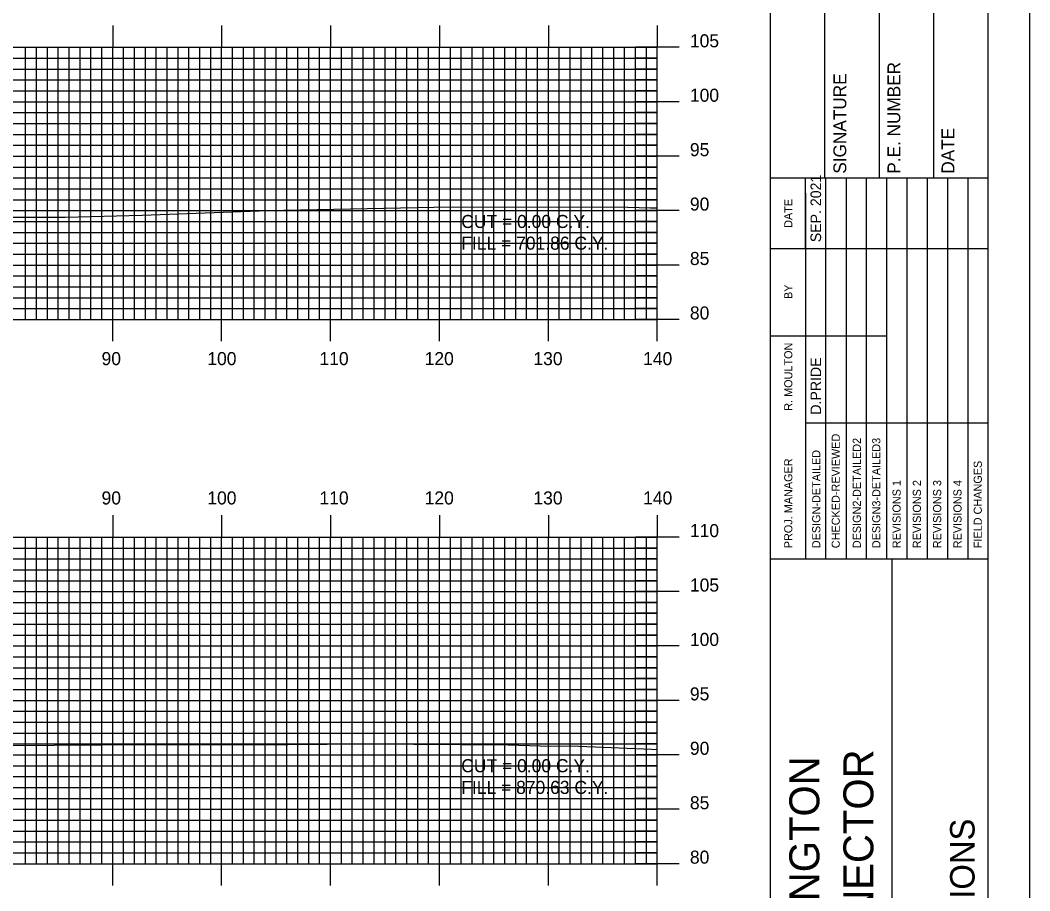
# Model space of a CAD drawing. Extents: x 1272 to 1616, y -1658 to -1438.
# Drawn here: x 1519.7 to 1612.4, y -1592.1 to -1512.1 of the extents above; entities that cross this region are included whole.
import ezdxf

# ---------------------------------------------------------------- set-up
doc = ezdxf.new("R2010")
doc.units = 0
for name, color, linetype in [('BORDER', 7, 'Continuous'), ('D_Text_Standard', 7, 'Continuous'), ('H_V ANNOTATION', 7, 'Continuous'), ('MAJOR', 7, 'Continuous'), ('MINOR', 7, 'Continuous'), ('PLOT BOUNDARY', 7, 'Continuous'), ('S_Roadway_Centerline', 7, 'Continuous')]:
    doc.layers.add(name, color=color, linetype=linetype)

msp = doc.modelspace()

# ---------------------------------------------------------------- linework, layer by layer
at = {"layer": 'BORDER'}
for p, q in [((1588.561, -1651.604), (1588.561, -1441.604)), ((1593.561, -1526.599), (1593.561, -1509.304)), ((1598.561, -1526.599), (1598.561, -1509.304)), ((1603.561, -1526.599), (1603.561, -1509.304)), ((1588.561, -1526.599), (1608.561, -1526.599)), ((1588.561, -1561.599), (1608.561, -1561.599)), ((1599.743, -1631.599), (1599.743, -1561.599))]:
    msp.add_line(p, q, dxfattribs=at)
msp.add_lwpolyline([(1288.561, -1651.604), (1608.561, -1651.604), (1608.561, -1441.604), (1288.561, -1441.604)], close=True, dxfattribs=at)
for points in [[(1591.79, -1533.099), (1591.79, -1526.599)], [(1593.655, -1561.593), (1593.655, -1526.599)], [(1595.519, -1526.599), (1595.519, -1561.593)], [(1597.382, -1561.593), (1597.382, -1526.599)], [(1599.246, -1561.593), (1599.246, -1526.599)], [(1601.109, -1561.593), (1601.109, -1526.599)], [(1602.972, -1561.593), (1602.972, -1526.599)], [(1604.836, -1561.593), (1604.836, -1526.599)], [(1606.699, -1561.593), (1606.699, -1526.599)], [(1591.792, -1561.593), (1591.792, -1528.01)], [(1588.561, -1533.099), (1608.561, -1533.099)], [(1588.561, -1541.099), (1591.792, -1541.099)], [(1591.79, -1541.099), (1599.244, -1541.099)], [(1591.79, -1549.099), (1608.561, -1549.099)]]:
    msp.add_lwpolyline(points, dxfattribs=at)
at = {"layer": 'MAJOR'}
for p, q in [((1528.161, -1512.6), (1528.161, -1514.604)), ((1538.161, -1512.6), (1538.161, -1514.604)), ((1548.161, -1512.6), (1548.161, -1514.604)), ((1558.161, -1512.6), (1558.161, -1514.604)), ((1568.161, -1512.6), (1568.161, -1514.604)), ((1578.161, -1512.6), (1578.161, -1514.604)), ((1298.161, -1514.604), (1578.161, -1514.604)), ((1298.161, -1514.604), (1578.161, -1514.604)), ((1528.161, -1539.604), (1528.161, -1514.604)), ((1538.161, -1539.604), (1538.161, -1514.604)), ((1548.161, -1539.604), (1548.161, -1514.604)), ((1558.161, -1539.604), (1558.161, -1514.604)), ((1568.161, -1539.604), (1568.161, -1514.604)), ((1580.165, -1514.604), (1576.157, -1514.604)), ((1578.161, -1539.604), (1578.161, -1514.604)), ((1578.161, -1539.604), (1578.161, -1514.604)), ((1298.161, -1519.604), (1578.161, -1519.604)), ((1580.165, -1519.604), (1576.157, -1519.604)), ((1298.161, -1524.604), (1578.161, -1524.604)), ((1580.165, -1524.604), (1576.157, -1524.604)), ((1298.161, -1529.604), (1578.161, -1529.604)), ((1580.165, -1529.604), (1576.157, -1529.604)), ((1298.161, -1534.604), (1578.161, -1534.604)), ((1580.165, -1534.604), (1576.157, -1534.604)), ((1298.161, -1539.604), (1578.161, -1539.604)), ((1298.161, -1539.604), (1578.161, -1539.604)), ((1528.161, -1541.608), (1528.161, -1539.604)), ((1538.161, -1541.608), (1538.161, -1539.604)), ((1548.161, -1541.608), (1548.161, -1539.604)), ((1558.161, -1541.608), (1558.161, -1539.604)), ((1568.161, -1541.608), (1568.161, -1539.604)), ((1580.165, -1539.604), (1576.157, -1539.604)), ((1578.161, -1541.608), (1578.161, -1539.604)), ((1528.161, -1557.6), (1528.161, -1559.604)), ((1538.161, -1557.6), (1538.161, -1559.604)), ((1548.161, -1557.6), (1548.161, -1559.604)), ((1558.161, -1557.6), (1558.161, -1559.604)), ((1568.161, -1557.6), (1568.161, -1559.604)), ((1578.161, -1557.6), (1578.161, -1559.604)), ((1298.161, -1559.604), (1578.161, -1559.604)), ((1298.161, -1559.604), (1578.161, -1559.604)), ((1528.161, -1589.604), (1528.161, -1559.604)), ((1538.161, -1589.604), (1538.161, -1559.604)), ((1548.161, -1589.604), (1548.161, -1559.604)), ((1558.161, -1589.604), (1558.161, -1559.604)), ((1568.161, -1589.604), (1568.161, -1559.604)), ((1580.165, -1559.604), (1576.157, -1559.604)), ((1578.161, -1589.604), (1578.161, -1559.604)), ((1578.161, -1589.604), (1578.161, -1559.604)), ((1298.161, -1564.604), (1578.161, -1564.604)), ((1580.165, -1564.604), (1576.157, -1564.604)), ((1298.161, -1569.604), (1578.161, -1569.604)), ((1580.165, -1569.604), (1576.157, -1569.604)), ((1298.161, -1574.604), (1578.161, -1574.604)), ((1580.165, -1574.604), (1576.157, -1574.604)), ((1298.161, -1579.604), (1578.161, -1579.604)), ((1580.165, -1579.604), (1576.157, -1579.604)), ((1298.161, -1584.604), (1578.161, -1584.604)), ((1580.165, -1584.604), (1576.157, -1584.604)), ((1298.161, -1589.604), (1578.161, -1589.604)), ((1298.161, -1589.604), (1578.161, -1589.604)), ((1528.161, -1591.608), (1528.161, -1589.604)), ((1538.161, -1591.608), (1538.161, -1589.604)), ((1548.161, -1591.608), (1548.161, -1589.604)), ((1558.161, -1591.608), (1558.161, -1589.604)), ((1568.161, -1591.608), (1568.161, -1589.604)), ((1580.165, -1589.604), (1576.157, -1589.604)), ((1578.161, -1591.608), (1578.161, -1589.604))]:
    msp.add_line(p, q, dxfattribs=at)
at = {"layer": 'MINOR'}
for p, q in [((1520.161, -1539.604), (1520.161, -1514.604)), ((1521.161, -1539.604), (1521.161, -1514.604)), ((1522.161, -1539.604), (1522.161, -1514.604)), ((1523.161, -1539.604), (1523.161, -1514.604)), ((1524.161, -1539.604), (1524.161, -1514.604)), ((1525.161, -1539.604), (1525.161, -1514.604)), ((1526.161, -1539.604), (1526.161, -1514.604)), ((1527.161, -1539.604), (1527.161, -1514.604)), ((1529.161, -1539.604), (1529.161, -1514.604)), ((1530.161, -1539.604), (1530.161, -1514.604)), ((1531.161, -1539.604), (1531.161, -1514.604)), ((1532.161, -1539.604), (1532.161, -1514.604)), ((1533.161, -1539.604), (1533.161, -1514.604)), ((1534.161, -1539.604), (1534.161, -1514.604)), ((1535.161, -1539.604), (1535.161, -1514.604)), ((1536.161, -1539.604), (1536.161, -1514.604)), ((1537.161, -1539.604), (1537.161, -1514.604)), ((1539.161, -1539.604), (1539.161, -1514.604)), ((1540.161, -1539.604), (1540.161, -1514.604)), ((1541.161, -1539.604), (1541.161, -1514.604)), ((1542.161, -1539.604), (1542.161, -1514.604)), ((1543.161, -1539.604), (1543.161, -1514.604)), ((1544.161, -1539.604), (1544.161, -1514.604)), ((1545.161, -1539.604), (1545.161, -1514.604)), ((1546.161, -1539.604), (1546.161, -1514.604)), ((1547.161, -1539.604), (1547.161, -1514.604)), ((1549.161, -1539.604), (1549.161, -1514.604)), ((1550.161, -1539.604), (1550.161, -1514.604)), ((1551.161, -1539.604), (1551.161, -1514.604)), ((1552.161, -1539.604), (1552.161, -1514.604)), ((1553.161, -1539.604), (1553.161, -1514.604)), ((1554.161, -1539.604), (1554.161, -1514.604)), ((1555.161, -1539.604), (1555.161, -1514.604)), ((1556.161, -1539.604), (1556.161, -1514.604)), ((1557.161, -1539.604), (1557.161, -1514.604)), ((1559.161, -1539.604), (1559.161, -1514.604)), ((1560.161, -1539.604), (1560.161, -1514.604)), ((1561.161, -1539.604), (1561.161, -1514.604)), ((1562.161, -1539.604), (1562.161, -1514.604)), ((1563.161, -1539.604), (1563.161, -1514.604)), ((1564.161, -1539.604), (1564.161, -1514.604)), ((1565.161, -1539.604), (1565.161, -1514.604)), ((1566.161, -1539.604), (1566.161, -1514.604)), ((1567.161, -1539.604), (1567.161, -1514.604)), ((1569.161, -1539.604), (1569.161, -1514.604)), ((1570.161, -1539.604), (1570.161, -1514.604)), ((1571.161, -1539.604), (1571.161, -1514.604)), ((1572.161, -1539.604), (1572.161, -1514.604)), ((1573.161, -1539.604), (1573.161, -1514.604)), ((1574.161, -1539.604), (1574.161, -1514.604)), ((1575.161, -1539.604), (1575.161, -1514.604)), ((1576.161, -1539.604), (1576.161, -1514.604)), ((1577.161, -1539.604), (1577.161, -1514.604)), ((1298.161, -1515.604), (1578.161, -1515.604)), ((1578.161, -1515.604), (1576.157, -1515.604)), ((1298.161, -1516.604), (1578.161, -1516.604)), ((1578.161, -1516.604), (1576.157, -1516.604)), ((1298.161, -1517.604), (1578.161, -1517.604)), ((1578.161, -1517.604), (1576.157, -1517.604)), ((1298.161, -1518.604), (1578.161, -1518.604)), ((1578.161, -1518.604), (1576.157, -1518.604)), ((1298.161, -1520.604), (1578.161, -1520.604)), ((1578.161, -1520.604), (1576.157, -1520.604)), ((1298.161, -1521.604), (1578.161, -1521.604)), ((1578.161, -1521.604), (1576.157, -1521.604)), ((1298.161, -1522.604), (1578.161, -1522.604)), ((1578.161, -1522.604), (1576.157, -1522.604)), ((1298.161, -1523.604), (1578.161, -1523.604)), ((1578.161, -1523.604), (1576.157, -1523.604)), ((1298.161, -1525.604), (1578.161, -1525.604)), ((1578.161, -1525.604), (1576.157, -1525.604)), ((1298.161, -1526.604), (1578.161, -1526.604)), ((1578.161, -1526.604), (1576.157, -1526.604)), ((1298.161, -1527.604), (1578.161, -1527.604)), ((1578.161, -1527.604), (1576.157, -1527.604)), ((1298.161, -1528.604), (1578.161, -1528.604)), ((1578.161, -1528.604), (1576.157, -1528.604)), ((1298.161, -1530.604), (1578.161, -1530.604)), ((1578.161, -1530.604), (1576.157, -1530.604)), ((1298.161, -1531.604), (1578.161, -1531.604)), ((1578.161, -1531.604), (1576.157, -1531.604)), ((1298.161, -1532.604), (1578.161, -1532.604)), ((1578.161, -1532.604), (1576.157, -1532.604)), ((1298.161, -1533.604), (1578.161, -1533.604)), ((1578.161, -1533.604), (1576.157, -1533.604)), ((1298.161, -1535.604), (1578.161, -1535.604)), ((1578.161, -1535.604), (1576.157, -1535.604)), ((1298.161, -1536.604), (1578.161, -1536.604)), ((1578.161, -1536.604), (1576.157, -1536.604)), ((1298.161, -1537.604), (1578.161, -1537.604)), ((1578.161, -1537.604), (1576.157, -1537.604)), ((1298.161, -1538.604), (1578.161, -1538.604)), ((1578.161, -1538.604), (1576.157, -1538.604)), ((1520.161, -1589.604), (1520.161, -1559.604)), ((1521.161, -1589.604), (1521.161, -1559.604)), ((1522.161, -1589.604), (1522.161, -1559.604)), ((1523.161, -1589.604), (1523.161, -1559.604)), ((1524.161, -1589.604), (1524.161, -1559.604)), ((1525.161, -1589.604), (1525.161, -1559.604)), ((1526.161, -1589.604), (1526.161, -1559.604)), ((1527.161, -1589.604), (1527.161, -1559.604)), ((1529.161, -1589.604), (1529.161, -1559.604)), ((1530.161, -1589.604), (1530.161, -1559.604)), ((1531.161, -1589.604), (1531.161, -1559.604)), ((1532.161, -1589.604), (1532.161, -1559.604)), ((1533.161, -1589.604), (1533.161, -1559.604)), ((1534.161, -1589.604), (1534.161, -1559.604)), ((1535.161, -1589.604), (1535.161, -1559.604)), ((1536.161, -1589.604), (1536.161, -1559.604)), ((1537.161, -1589.604), (1537.161, -1559.604)), ((1539.161, -1589.604), (1539.161, -1559.604)), ((1540.161, -1589.604), (1540.161, -1559.604)), ((1541.161, -1589.604), (1541.161, -1559.604)), ((1542.161, -1589.604), (1542.161, -1559.604)), ((1543.161, -1589.604), (1543.161, -1559.604)), ((1544.161, -1589.604), (1544.161, -1559.604)), ((1545.161, -1589.604), (1545.161, -1559.604)), ((1546.161, -1589.604), (1546.161, -1559.604)), ((1547.161, -1589.604), (1547.161, -1559.604)), ((1549.161, -1589.604), (1549.161, -1559.604)), ((1550.161, -1589.604), (1550.161, -1559.604)), ((1551.161, -1589.604), (1551.161, -1559.604)), ((1552.161, -1589.604), (1552.161, -1559.604)), ((1553.161, -1589.604), (1553.161, -1559.604)), ((1554.161, -1589.604), (1554.161, -1559.604)), ((1555.161, -1589.604), (1555.161, -1559.604)), ((1556.161, -1589.604), (1556.161, -1559.604)), ((1557.161, -1589.604), (1557.161, -1559.604)), ((1559.161, -1589.604), (1559.161, -1559.604)), ((1560.161, -1589.604), (1560.161, -1559.604)), ((1561.161, -1589.604), (1561.161, -1559.604)), ((1562.161, -1589.604), (1562.161, -1559.604)), ((1563.161, -1589.604), (1563.161, -1559.604)), ((1564.161, -1589.604), (1564.161, -1559.604)), ((1565.161, -1589.604), (1565.161, -1559.604)), ((1566.161, -1589.604), (1566.161, -1559.604)), ((1567.161, -1589.604), (1567.161, -1559.604)), ((1569.161, -1589.604), (1569.161, -1559.604)), ((1570.161, -1589.604), (1570.161, -1559.604)), ((1571.161, -1589.604), (1571.161, -1559.604)), ((1572.161, -1589.604), (1572.161, -1559.604)), ((1573.161, -1589.604), (1573.161, -1559.604)), ((1574.161, -1589.604), (1574.161, -1559.604)), ((1575.161, -1589.604), (1575.161, -1559.604)), ((1576.161, -1589.604), (1576.161, -1559.604)), ((1577.161, -1589.604), (1577.161, -1559.604)), ((1298.161, -1560.604), (1578.161, -1560.604)), ((1578.161, -1560.604), (1576.157, -1560.604)), ((1298.161, -1561.604), (1578.161, -1561.604)), ((1578.161, -1561.604), (1576.157, -1561.604)), ((1298.161, -1562.604), (1578.161, -1562.604)), ((1578.161, -1562.604), (1576.157, -1562.604)), ((1298.161, -1563.604), (1578.161, -1563.604)), ((1578.161, -1563.604), (1576.157, -1563.604)), ((1298.161, -1565.604), (1578.161, -1565.604)), ((1578.161, -1565.604), (1576.157, -1565.604)), ((1298.161, -1566.604), (1578.161, -1566.604)), ((1578.161, -1566.604), (1576.157, -1566.604)), ((1298.161, -1567.604), (1578.161, -1567.604)), ((1578.161, -1567.604), (1576.157, -1567.604)), ((1298.161, -1568.604), (1578.161, -1568.604)), ((1578.161, -1568.604), (1576.157, -1568.604)), ((1298.161, -1570.604), (1578.161, -1570.604)), ((1578.161, -1570.604), (1576.157, -1570.604)), ((1298.161, -1571.604), (1578.161, -1571.604)), ((1578.161, -1571.604), (1576.157, -1571.604)), ((1298.161, -1572.604), (1578.161, -1572.604)), ((1578.161, -1572.604), (1576.157, -1572.604)), ((1298.161, -1573.604), (1578.161, -1573.604)), ((1578.161, -1573.604), (1576.157, -1573.604)), ((1298.161, -1575.604), (1578.161, -1575.604)), ((1578.161, -1575.604), (1576.157, -1575.604)), ((1298.161, -1576.604), (1578.161, -1576.604)), ((1578.161, -1576.604), (1576.157, -1576.604)), ((1298.161, -1577.604), (1578.161, -1577.604)), ((1578.161, -1577.604), (1576.157, -1577.604)), ((1298.161, -1578.604), (1578.161, -1578.604)), ((1578.161, -1578.604), (1576.157, -1578.604)), ((1298.161, -1580.604), (1578.161, -1580.604)), ((1578.161, -1580.604), (1576.157, -1580.604)), ((1298.161, -1581.604), (1578.161, -1581.604)), ((1578.161, -1581.604), (1576.157, -1581.604)), ((1298.161, -1582.604), (1578.161, -1582.604)), ((1578.161, -1582.604), (1576.157, -1582.604)), ((1298.161, -1583.604), (1578.161, -1583.604)), ((1578.161, -1583.604), (1576.157, -1583.604)), ((1298.161, -1585.604), (1578.161, -1585.604)), ((1578.161, -1585.604), (1576.157, -1585.604)), ((1298.161, -1586.604), (1578.161, -1586.604)), ((1578.161, -1586.604), (1576.157, -1586.604)), ((1298.161, -1587.604), (1578.161, -1587.604)), ((1578.161, -1587.604), (1576.157, -1587.604)), ((1298.161, -1588.604), (1578.161, -1588.604)), ((1578.161, -1588.604), (1576.157, -1588.604))]:
    msp.add_line(p, q, dxfattribs=at)
at = {"layer": 'PLOT BOUNDARY'}
msp.add_lwpolyline([(1272.374, -1657.723), (1612.374, -1657.723), (1612.374, -1437.723), (1272.374, -1437.723)], close=True, dxfattribs=at)
at = {"layer": 'S_Roadway_Centerline'}
for points in [[(1413.396, -1529.961), (1429.638, -1530.096), (1430.822, -1530.149), (1431.448, -1530.135), (1444.005, -1529.703), (1450.781, -1529.82), (1468.074, -1529.741), (1468.298, -1529.743), (1468.536, -1529.743), (1486.823, -1529.98), (1503.187, -1529.846), (1504.706, -1529.859), (1506.515, -1529.882), (1517.922, -1530.201), (1523.796, -1530.205), (1530.869, -1530.037), (1541.617, -1529.637), (1542.342, -1529.609), (1559.166, -1529.257), (1575.461, -1529.304), (1577.547, -1529.348), (1578.161, -1529.362)], [(1417.658, -1579.206), (1430.508, -1579.166), (1440.39, -1579.411), (1447.767, -1579.456), (1459.45, -1579.436), (1463.488, -1579.342), (1472.434, -1579.118), (1478.76, -1578.945), (1480.566, -1578.936), (1492.453, -1579.044), (1499.139, -1578.843), (1513.318, -1578.791), (1515.997, -1578.759), (1517.24, -1578.738), (1522.793, -1578.712), (1531.635, -1578.65), (1533.45, -1578.669), (1544.236, -1578.641), (1551.493, -1578.592), (1564.482, -1578.691), (1568.385, -1578.804), (1570.235, -1578.783), (1577.631, -1579.099), (1578.161, -1579.116)]]:
    msp.add_lwpolyline(points, dxfattribs=at)

# ---------------------------------------------------------------- texts
at = {"layer": 'BORDER'}
for s, height, p in [('P.E. NUMBER', 1.1811, (1600.482, -1526.214)), ('SIGNATURE', 1.1811, (1595.521, -1526.214)), ('DATE', 1.1811, (1605.443, -1526.214)), ('SEP. 2021', 0.9691, (1593.206, -1532.507)), ('DATE', 0.7428, (1590.569, -1531.187)), ('BY', 0.7428, (1590.569, -1537.728)), ('R. MOULTON', 0.7455, (1590.569, -1547.994)), ('D.PRIDE', 0.9691, (1593.206, -1548.352)), ('CHECKED-REVIEWED', 0.7455, (1594.923, -1560.622)), ('DESIGN2-DETAILED2', 0.7455, (1596.86, -1560.622)), ('DESIGN3-DETAILED3', 0.7455, (1598.649, -1560.622)), ('DESIGN-DETAILED', 0.7455, (1593.134, -1560.622)), ('PROJ. MANAGER', 0.7455, (1590.569, -1560.622)), ('FIELD CHANGES', 0.7455, (1607.966, -1560.622)), ('REVISIONS 1', 0.7455, (1600.513, -1560.622)), ('REVISIONS 2', 0.7455, (1602.376, -1560.622)), ('REVISIONS 3', 0.7455, (1604.239, -1560.622)), ('REVISIONS 4', 0.7455, (1606.103, -1560.622)), ('I-395/ROUTE 9 CONNECTOR', 2.75575, (1598.01, -1629.274)), ('BREWER TO EDDINGTON', 2.75575, (1593.049, -1625.195)), ('CROSS SECTIONS', 2.25, (1607.302, -1612.383))]:
    msp.add_text(s, height=height, rotation=90, dxfattribs=at).set_placement(p)
at = {"layer": 'D_Text_Standard'}
for s, p in [('CUT = 0.00 C.Y.', (1560.161, -1531.204)), ('FILL = 701.86 C.Y.', (1560.161, -1533.196)), ('CUT = 0.00 C.Y.', (1560.161, -1581.204)), ('FILL = 870.63 C.Y.', (1560.161, -1583.196))]:
    msp.add_text(s, height=1.2, dxfattribs=at).set_placement(p)
at = {"layer": 'H_V ANNOTATION'}
for s, p in [('105', (1581.161, -1514.604)), ('100', (1581.161, -1519.604)), ('95', (1581.161, -1524.604)), ('90', (1581.161, -1529.604)), ('85', (1581.161, -1534.604)), ('80', (1581.161, -1539.604)), ('90', (1527.133, -1543.804)), ('100', (1536.844, -1543.804)), ('110', (1547.144, -1543.804)), ('120', (1556.801, -1543.804)), ('130', (1566.79, -1543.804)), ('140', (1576.865, -1543.804)), ('90', (1527.133, -1556.604)), ('100', (1536.844, -1556.604)), ('110', (1547.144, -1556.604)), ('120', (1556.801, -1556.604)), ('130', (1566.79, -1556.604)), ('140', (1576.865, -1556.604)), ('110', (1581.161, -1559.604)), ('105', (1581.161, -1564.604)), ('100', (1581.161, -1569.604)), ('95', (1581.161, -1574.604)), ('90', (1581.161, -1579.604)), ('85', (1581.161, -1584.604)), ('80', (1581.161, -1589.604))]:
    msp.add_text(s, height=1.2, dxfattribs=at).set_placement(p)

doc.saveas('drawing.dxf')
